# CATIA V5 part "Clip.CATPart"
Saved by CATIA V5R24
Part number: Clip
Material "Steel": density 7860 kg/m3, Young's modulus 2e+11 Pa, Poisson ratio 0.266, thermal expansion 1.17e-05 1/K
Bounding box of the stored display mesh (mm): x -7.9 to 7.9, y -19 to -14.029, z 0 to 4.52
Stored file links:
  C:\Users\Jules\Documents\ECL\Watch\Clip.CATPart
  C:\Users\Jules\Documents\ECL\Watch\Midle link.CATPart
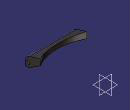
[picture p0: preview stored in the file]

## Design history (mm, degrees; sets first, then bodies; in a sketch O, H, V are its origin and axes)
Body1 (main body)
  Sketch1 on xy-plane, origin (0, 0, 0), H (1, 0, 0), V (0, 1, 0)
    construction arc A1 centre (0, 0) radius 16 from (-13.9491, 7.8372) to (-13.9491, -7.8372) ccw
    point P1 (-8, 13.8564)
    construction line L1 (-8, 13.8564) -> (-8, 19)
    point P2 (-8, 19)
    construction line L2 (-8, 19) -> (-9.5, 19)
    point P3 (-9.5, 19)
    construction line L3 (-9.5, 19) -> (-10.7872, 15.0465)
    point P4 (-12.3901, 10.1236)
    construction arc A2 centre (-48.822, 27.4301) radius 40 from (-13.9491, 7.8372) to (-10.7872, 15.0465) ccw
    point P5 (-13.9491, 7.8372)
    point P6 (-10.7872, 15.0465)
    point P7 (-8, 13.8564)
    point P9 (10.7872, 15.0465)
    point P10 (13.9491, 7.8372)
    construction arc A3 centre (48.822, 27.4301) radius 40 from (13.9491, 7.8372) to (10.7872, 15.0465) cw
    point P12 (9.5, 19)
    construction line L4 (9.5, 19) -> (10.7872, 15.0465)
    point P13 (8, 19)
    construction line L5 (8, 19) -> (9.5, 19)
    point P14 (8, 13.8564)
    construction line L6 (8, 13.8564) -> (8, 19)
    point P15 (10.7872, -15.0465)
    point P16 (13.9491, -7.8372)
    construction arc A4 centre (48.822, -27.4301) radius 40 from (13.9491, -7.8372) to (10.7872, -15.0465) ccw
    point P18 (9.5, -19)
    point P19 (8, -19)
    construction line L7 (8, -19) -> (9.5, -19)
    construction line L8 (9.5, -19) -> (10.7872, -15.0465)
    point P20 (8, -13.8564)
    construction line L9 (8, -13.8564) -> (8, -19)
    point P21 (-8, -19)
    point P22 (-8, -13.8564)
    construction line L10 (-8, -13.8564) -> (-8, -19)
    point P23 (-9.5, -19)
    construction line L11 (-8, -19) -> (-9.5, -19)
    point P24 (-10.7872, -15.0465)
    construction line L12 (-9.5, -19) -> (-10.7872, -15.0465)
    point P25 (-13.9491, -7.8372)
    construction arc A5 centre (-48.822, -27.4301) radius 40 from (-13.9491, -7.8372) to (-10.7872, -15.0465) cw
    construction arc A6 centre (0, 0) radius 16 from (8, 13.8564) to (-8, 13.8564) ccw
    construction arc A7 centre (0, 0) radius 16 from (13.9491, -7.8372) to (13.9491, 7.8372) ccw
    construction arc A8 centre (0, 0) radius 16 from (-8, -13.8564) to (8, -13.8564) ccw
    point P27 (-7.9, -19)
    line L13 (-7.9, -19) -> (-7.9, -14.0285)
    line L14 (-7.9, -19) -> (7.9, -19)
    line L15 (7.9, -19) -> (7.9, -14.0285)
    arc A9 centre (0, 0) radius 16.1 from (-7.9, -14.0285) to (7.9, -14.0285) ccw
    point P31 (0, 0)
    point P32 (0, -16.1)
    radius A2 = 40
    radius A1 = 16
    distance L1 V = 8
    distance H P3 = 19
    length L2 = 1.5
    distance A8 A9 = 0.1
    distance L15 L9 = 0.1
    distance L13 L10 = 0.1
    coincidence: P1 A1, P4 A1, L3 P4, P7 P1, A1 A6, A1 A7, A1 A8, P27 L7, A9 P32, P32 V, P31 O
    vertical: L1 V, L13 V, L15 V
    horizontal: L2 H, L14 H
    tangency: A2 L3, A2 A1
    symmetry: P6 P9 V, P5 P10 V, A2 A3 V, P3 P12 V, L3 L4 V, P2 P13 V, L2 L5 V, P1 P14 V, L1 L6 V, P9 P15 H, P10 P16 H, A3 A4 H, P12 P18 H, P13 P19 H, L5 L7 H, L4 L8 H, P14 P20 H, L6 L9 H, P2 P21 H, P1 P22 H, L1 L10 H, P3 P23 H, L2 L11 H, P6 P24 H, L3 L12 H, P5 P25 H, A2 A5 H
  Pad1: profile Sketch1, direction (0, 0, 1), length 5.5
  Sketch2 on zx-plane, origin (0, 0, 0), H (-1, 0, 0), V (0, 0, 1)
    point P1 (-16, 2.5)
    line L1 (-16, 2.5) -> (-19.5704, 0)
    point P2 (-19.5704, 0)
    line L2 (-19.5704, 0) -> (-13.5, 0)
    line L3 (-13.5, 0) -> (-16, 2.5)
    angle L1 L2 = 35
    angle L3 L2 = 45
    distance L2 P1 = 2.5
    coincidence: P2 H
    horizontal: L2 H
  Groove1: profile Sketch2, axis Sketch2.V, angle 360
  Sketch3 on yz-plane, origin (0, 0, 0), H (0, 1, 0), V (0, 0, 1)
    point P1 (-19, 3)
    line L1 (-19, 3) -> (0, 8.8089)
    point P2 (0, 8.8089)
    reference projected line E1 through (0, 0) direction (0, 1) from axis of face of Groove1 from Sketch2.L3
    point P5 (0, 8.8089)
    point P6 (19, 3)
    line L2 (19, 3) -> (0, 8.8089)
    distance P1 H = 3
    angle L1 H = 17
    coincidence: P2 V, P2 P5
    symmetry: P2 P5 E1, P1 P6 E1, L1 L2 E1
  Pocket1: profile Sketch3, direction (-1, 0, 0), length 10, mirrored extent, thin wall 0, second thickness 5
  Fillet1: radius 2, on edge [face of Pocket1 | face of Pad1 from Sketch1.L14]
  Sketch4 on yz-plane, origin (0, 0, 0), H (0, 1, 0), V (0, 0, 1)
    line L1 (-21, 2.85) -> (-18, 2.85)
    arc A1 centre (-18, 1.4) radius 1.45 from (-18, 2.85) to (-16.5731, 1.658) cw
    point P3 (-18, 1.4)
    point P4 (-18.0483, -0.0492)
    point P5 (-21.0467, 0.0508)
    arc A2 centre (-21, 1.45) radius 1.4 from (-21.7039, 0.2398) to (-21, 2.85) cw
    construction circle A3 centre (-18, 1.4) radius 0.55
    construction circle A4 centre (-21, 1.45) radius 0.55
    line L2 (-16.5731, 1.658) -> (-16.021, -1.3948)
    line L3 (-16.021, -1.3948) -> (-21.7039, 0.2398)
    radius A1 = 1.45
    distance P3 V = 18
    radius A3 = 0.55
    radius A4 = 0.55
    distance P3 H = 1.4
    distance P4 P5 = 3
    horizontal: L1 H
    tangency: A1 L1, A2 L1, L2 A1
    coincidence: L3 P5
  Pocket2: profile Sketch4, direction (-1, 0, 0), length 4.5, mirrored extent
  Sketch5 on yz-plane, origin (0, 0, 0), H (0, 1, 0), V (0, 0, 1)
    construction line L1 (-21, 2.85) -> (-18, 2.85)
    construction arc A1 centre (-18, 1.4) radius 1.45 from (-18, 2.85) to (-16.5731, 1.658) cw
    point P3 (-18, 1.4)
    point P4 (-18.0483, -0.0492)
    point P5 (-21.0467, 0.0508)
    construction arc A2 centre (-21, 1.45) radius 1.4 from (-21.7039, 0.2398) to (-21, 2.85) cw
    circle A3 centre (-18, 1.4) radius 0.55
    construction circle A4 centre (-21, 1.45) radius 0.55
    construction line L2 (-16.5731, 1.658) -> (-16.021, -1.3948)
    construction line L3 (-16.021, -1.3948) -> (-21.7039, 0.2398)
    radius A1 = 1.45
    distance P3 V = 18
    radius A3 = 0.55
    radius A4 = 0.55
    distance P3 H = 1.4
    distance P4 P5 = 3
    horizontal: L1 H
    tangency: A1 L1, A2 L1, L2 A1
    coincidence: L3 P5
  Pocket3: profile Sketch5, direction (-1, 0, 0), length 8.7, mirrored extent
